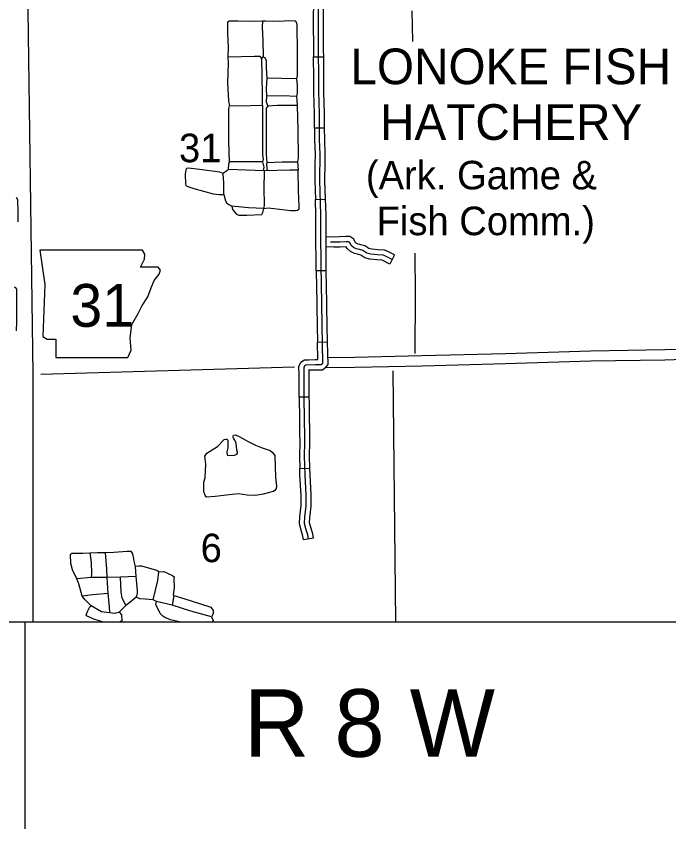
# Model space of a CAD drawing. Extents: x 1127717 to 1741049, y 2026793 to 2244711.
# Drawn here: x 1338119 to 1347778, y 2063612 to 2075639 of the extents above; entities that cross this region are included whole.
import ezdxf

# ---------------------------------------------------------------- set-up
doc = ezdxf.new("R2010")
doc.units = 0
for name, color, linetype in [('1', 7, 'Continuous'), ('10', 7, 'Continuous'), ('21', 7, 'Continuous'), ('31', 7, 'Continuous'), ('35', 7, 'Continuous'), ('37', 7, 'Continuous'), ('4', 7, 'Continuous'), ('45', 7, 'Continuous'), ('46', 7, 'Continuous'), ('5', 7, 'Continuous'), ('7', 7, 'Continuous'), ('R_Draft', 7, 'Continuous')]:
    doc.layers.add(name, color=color, linetype=linetype)

msp = doc.modelspace()

# ---------------------------------------------------------------- linework, layer by layer
at = {"layer": '1'}
msp.add_line((1338244, 2066677), (1338244, 2063612), dxfattribs=at)
msp.add_lwpolyline([(1349634, 2111942), (1278363, 2111942), (1278363, 2066677), (1349634, 2066677)], close=True, dxfattribs=at)
at = {"layer": '10'}
for points in [[(1338278, 2076445), (1338363, 2070341)], [(1338363, 2070339), (1338362, 2066677)]]:
    msp.add_lwpolyline(points, dxfattribs=at)
at = {"layer": '21'}
msp.add_lwpolyline([(1338468, 2072178), (1338544, 2071670), (1338510, 2070900), (1338578, 2070858), (1338705, 2070858), (1338705, 2070587), (1339771, 2070587), (1339821, 2070697), (1339804, 2070875), (1339830, 2071078), (1339923, 2071239), (1339982, 2071357), (1340067, 2071484), (1340117, 2071619), (1340160, 2071729), (1340236, 2071822), (1340253, 2071882), (1340219, 2071924), (1339957, 2071924), (1340016, 2072042), (1340024, 2072118), (1339989, 2072177)], close=True, dxfattribs=at)
at = {"layer": '31'}
for p, q in [((1342520, 2075038), (1342670, 2075039)), ((1342684, 2073983), (1342534, 2073982)), ((1342548, 2072924), (1342697, 2072929)), ((1342709, 2071872), (1342559, 2071869)), ((1342709, 2071872), (1342709, 2071872)), ((1342577, 2070813), (1342727, 2070817)), ((1342457, 2070002), (1342307, 2070002)), ((1342316, 2068944), (1342466, 2068948)), ((1342518, 2067911), (1342369, 2067888))]:
    msp.add_line(p, q, dxfattribs=at)
for points in [[(1342515, 2076093), (1342516, 2075947), (1342519, 2075852), (1342516, 2075591), (1342516, 2075566)], [(1342666, 2075567), (1342666, 2075590), (1342669, 2075854), (1342666, 2075950), (1342665, 2076095)], [(1342444, 2067900), (1342434, 2067961), (1342412, 2068034), (1342386, 2068131), (1342390, 2068222), (1342400, 2068306), (1342411, 2068391), (1342411, 2068551), (1342394, 2068853), (1342386, 2069125), (1342390, 2069333), (1342386, 2069748), (1342383, 2069921), (1342381, 2070338), (1342379, 2070441), (1342390, 2070468), (1342406, 2070477), (1342544, 2070482), (1342628, 2070482), (1342650, 2070497), (1342659, 2070510), (1342646, 2071056), (1342642, 2071395), (1342633, 2071945), (1342630, 2072444), (1342630, 2072697), (1342614, 2073211), (1342617, 2073595), (1342610, 2073813), (1342607, 2074196), (1342598, 2074529), (1342598, 2074724), (1342594, 2075137), (1342591, 2075591), (1342594, 2075853)], [(1342516, 2075566), (1342519, 2075136), (1342520, 2075038)], [(1342670, 2075039), (1342669, 2075137), (1342666, 2075567)], [(1342523, 2074508), (1342523, 2074528), (1342523, 2074724), (1342520, 2075038)], [(1342673, 2074512), (1342673, 2074530), (1342673, 2074724), (1342670, 2075039)], [(1342534, 2073982), (1342532, 2074195), (1342523, 2074508)], [(1342684, 2073983), (1342682, 2074198), (1342673, 2074512)], [(1342534, 2073982), (1342535, 2073811), (1342542, 2073594), (1342541, 2073455)], [(1342691, 2073454), (1342692, 2073596), (1342685, 2073814), (1342684, 2073983)], [(1342541, 2073455), (1342539, 2073211), (1342548, 2072924)], [(1342697, 2072929), (1342689, 2073212), (1342691, 2073454)], [(1342555, 2072398), (1342555, 2072444), (1342555, 2072695), (1342548, 2072924)], [(1342705, 2072399), (1342705, 2072444), (1342705, 2072698), (1342697, 2072929)], [(1342559, 2071869), (1342558, 2071944), (1342555, 2072398)], [(1342709, 2071872), (1342708, 2071946), (1342705, 2072399)], [(1342559, 2071869), (1342567, 2071394), (1342568, 2071342)], [(1342718, 2071344), (1342717, 2071396), (1342709, 2071872)], [(1342568, 2071342), (1342571, 2071055), (1342577, 2070813)], [(1342727, 2070817), (1342721, 2071057), (1342718, 2071344)], [(1342445, 2070553), (1342542, 2070557), (1342583, 2070557), (1342577, 2070813)], [(1342451, 2070403), (1342545, 2070407), (1342652, 2070407), (1342703, 2070443), (1342735, 2070486), (1342727, 2070817)], [(1342307, 2070002), (1342306, 2070337), (1342304, 2070455), (1342331, 2070519), (1342384, 2070551), (1342445, 2070553)], [(1342457, 2070002), (1342456, 2070338), (1342455, 2070404), (1342451, 2070403)], [(1342307, 2070002), (1342308, 2069921), (1342311, 2069747), (1342314, 2069473)], [(1342464, 2069475), (1342461, 2069749), (1342458, 2069922), (1342457, 2070002)], [(1342314, 2069473), (1342315, 2069333), (1342311, 2069125), (1342316, 2068944)], [(1342466, 2068948), (1342461, 2069125), (1342465, 2069333), (1342464, 2069475)], [(1342336, 2068419), (1342336, 2068548), (1342319, 2068849), (1342316, 2068944)], [(1342486, 2068419), (1342486, 2068553), (1342469, 2068856), (1342466, 2068948)], [(1342369, 2067888), (1342361, 2067944), (1342340, 2068014), (1342310, 2068123), (1342316, 2068228), (1342325, 2068315), (1342336, 2068396), (1342336, 2068419)], [(1342518, 2067911), (1342508, 2067977), (1342484, 2068055), (1342461, 2068139), (1342465, 2068216), (1342474, 2068297), (1342486, 2068386), (1342486, 2068419)]]:
    msp.add_lwpolyline(points, dxfattribs=at)
at = {"layer": '35'}
for points in [[(1341764, 2075564), (1341632, 2075562), (1341397, 2075564), (1341304, 2075568), (1341270, 2075568), (1341256, 2075560), (1341248, 2075547), (1341248, 2075394), (1341254, 2075173), (1341252, 2075035), (1341254, 2074944), (1341248, 2074655), (1341260, 2074380), (1341274, 2074314)], [(1342284, 2074320), (1342276, 2074390), (1342274, 2074453), (1342284, 2074501), (1342284, 2074617), (1342272, 2074712), (1342280, 2074764), (1342282, 2075092), (1342278, 2075515), (1342264, 2075555), (1342248, 2075568), (1342156, 2075570), (1342017, 2075560), (1341810, 2075568), (1341764, 2075564), (1341760, 2075481), (1341768, 2075278), (1341774, 2075037)], [(1341754, 2075013), (1341729, 2075041), (1341646, 2075043), (1341252, 2075035)], [(1341762, 2074320), (1341762, 2074483), (1341754, 2075013), (1341774, 2075037), (1341798, 2075029), (1341818, 2074983), (1341820, 2074876), (1341827, 2074724), (1341818, 2074576), (1341825, 2074455), (1341816, 2074372), (1341843, 2074309)], [(1342272, 2074712), (1342043, 2074718), (1341827, 2074724)], [(1342274, 2074453), (1342059, 2074463), (1341825, 2074455)], [(1341262, 2073372), (1341264, 2073454), (1341274, 2073486), (1341266, 2073789), (1341268, 2074273), (1341274, 2074314), (1341588, 2074320), (1341727, 2074324), (1341762, 2074320), (1341766, 2073990), (1341766, 2073581), (1341772, 2073528), (1341764, 2073486), (1341786, 2073407), (1341776, 2073353)], [(1342296, 2073360), (1342288, 2073484), (1342298, 2073543), (1342290, 2073953), (1342284, 2074320), (1341988, 2074316), (1341843, 2074309), (1341816, 2074277), (1341818, 2074168), (1341820, 2073593), (1341827, 2073476), (1341823, 2073447), (1341829, 2073389), (1341831, 2073353)], [(1341764, 2073486), (1341434, 2073484), (1341274, 2073486)], [(1341827, 2073476), (1342053, 2073482), (1342288, 2073484)], [(1342296, 2073360), (1342171, 2073358), (1341790, 2073352), (1341521, 2073358), (1341262, 2073372), (1341235, 2073352), (1341183, 2073313), (1341130, 2073333), (1340831, 2073370), (1340671, 2073392), (1340640, 2073386), (1340628, 2073366), (1340620, 2073299), (1340622, 2073153), (1340630, 2073131), (1340657, 2073121), (1340746, 2073089), (1341033, 2073010), (1341124, 2072998), (1341155, 2073002), (1341191, 2073002), (1341217, 2072904), (1341235, 2072870), (1341266, 2072852), (1341308, 2072828), (1341320, 2072777), (1341373, 2072712), (1341408, 2072692), (1341531, 2072692), (1341756, 2072702), (1341770, 2072732), (1341784, 2072791), (1341849, 2072803), (1342185, 2072761), (1342254, 2072761), (1342280, 2072767), (1342306, 2072789), (1342306, 2072823), (1342296, 2073060), (1342294, 2073356)], [(1341790, 2073352), (1341786, 2073080), (1341788, 2072860), (1341784, 2072791)], [(1341191, 2073002), (1341191, 2073168), (1341183, 2073313)], [(1338146, 2072594), (1338146, 2072746), (1338141, 2072920), (1338120, 2072957)], [(1341784, 2072791), (1341555, 2072805), (1341308, 2072828)], [(1338123, 2070982), (1338128, 2071114), (1338126, 2071283), (1338128, 2071528), (1338128, 2071601), (1338113, 2071621), (1338095, 2071627)], [(1341946, 2069136), (1341956, 2068817), (1341971, 2068684), (1341968, 2068648), (1341946, 2068619), (1341920, 2068605), (1341772, 2068564), (1341659, 2068546), (1341538, 2068552), (1341411, 2068568), (1341316, 2068558), (1341065, 2068530), (1340939, 2068522), (1340930, 2068527), (1340918, 2068539), (1340896, 2068597), (1340896, 2068740), (1340915, 2068807), (1340925, 2069007), (1340911, 2069128), (1340942, 2069171), (1341099, 2069268), (1341198, 2069374), (1341222, 2069379), (1341236, 2069379), (1341249, 2069362), (1341249, 2069334), (1341249, 2069251), (1341237, 2069193), (1341237, 2069174), (1341241, 2069153), (1341244, 2069143), (1341266, 2069138), (1341352, 2069140), (1341386, 2069155), (1341393, 2069169), (1341393, 2069186), (1341384, 2069217), (1341376, 2069317), (1341353, 2069363), (1341333, 2069392), (1341328, 2069401), (1341328, 2069430), (1341336, 2069437), (1341364, 2069444), (1341418, 2069420), (1341553, 2069343), (1341662, 2069290)], [(1341662, 2069290), (1341761, 2069249), (1341879, 2069211), (1341906, 2069188), (1341946, 2069136)], [(1339880, 2067495), (1339888, 2067348), (1339911, 2067139), (1339911, 2067084), (1339898, 2067062), (1339894, 2067041), (1339800, 2066959), (1339743, 2066914), (1339643, 2066816), (1339576, 2066800), (1339500, 2066806), (1339380, 2066823), (1339229, 2066912), (1339141, 2066998), (1339096, 2067057), (1339047, 2067239), (1339018, 2067311), (1338953, 2067444), (1338926, 2067538), (1338924, 2067670), (1338943, 2067691), (1338982, 2067693), (1339106, 2067689), (1339206, 2067695), (1339321, 2067703), (1339437, 2067703), (1339564, 2067707), (1339762, 2067723), (1339813, 2067719), (1339837, 2067693), (1339845, 2067662), (1339860, 2067572), (1339880, 2067495)], [(1339206, 2067695), (1339227, 2067554), (1339231, 2067388), (1339229, 2067329)], [(1339437, 2067703), (1339453, 2067456), (1339461, 2067331), (1339476, 2067092), (1339494, 2066904), (1339500, 2066806)], [(1340231, 2067415), (1340199, 2067433), (1339980, 2067501), (1339935, 2067501), (1339880, 2067495)], [(1339888, 2067348), (1339664, 2067335), (1339461, 2067331), (1339229, 2067329), (1339018, 2067311)], [(1339743, 2066914), (1339686, 2067031), (1339674, 2067115), (1339664, 2067335)], [(1340146, 2067000), (1340213, 2067286), (1340231, 2067415)], [(1340231, 2067415), (1340301, 2067419), (1340433, 2067360), (1340454, 2067341), (1340452, 2067315), (1340458, 2067178), (1340442, 2067076), (1340452, 2067064), (1340613, 2067017), (1340971, 2066904), (1340997, 2066890), (1341034, 2066841), (1341036, 2066800), (1341030, 2066784), (1341009, 2066751)], [(1339476, 2067092), (1339251, 2067076), (1339096, 2067057)], [(1341009, 2066751), (1340705, 2066833), (1340427, 2066919), (1340197, 2066976), (1340146, 2067000), (1340025, 2067010), (1339949, 2067017), (1339894, 2067041)], [(1340537, 2066677), (1340401, 2066706), (1340319, 2066737), (1340291, 2066757), (1340248, 2066800), (1340184, 2066929), (1340197, 2066976)], [(1340452, 2067064), (1340427, 2066919)], [(1339396, 2066677), (1339265, 2066716), (1339159, 2066761), (1339155, 2066776), (1339176, 2066837), (1339202, 2066886), (1339229, 2066912)], [(1339643, 2066816), (1339676, 2066778), (1339680, 2066688), (1339657, 2066677)], [(1341009, 2066751), (1341036, 2066694), (1341021, 2066677)]]:
    msp.add_lwpolyline(points, dxfattribs=at)
at = {"layer": '37'}
msp.add_lwpolyline([(1338468, 2066677), (1338468, 2066677)], dxfattribs=at)
at = {"layer": '4'}
msp.add_lwpolyline([(1338482, 2070340), (1342237, 2070450)], dxfattribs=at)
at = {"layer": '45'}
msp.add_line((1343717, 2072105), (1343650, 2071971), dxfattribs=at)
for points in [[(1343205, 2072261), (1343178, 2072267), (1343152, 2072281), (1343137, 2072293), (1343114, 2072339), (1343058, 2072377), (1343003, 2072377), (1342906, 2072372), (1342821, 2072370), (1342705, 2072375)], [(1343684, 2072038), (1343577, 2072092), (1343551, 2072103), (1343464, 2072106), (1343369, 2072117), (1343308, 2072134), (1343250, 2072169), (1343198, 2072185), (1343152, 2072197), (1343110, 2072218), (1343077, 2072246), (1343056, 2072288), (1343035, 2072302), (1343005, 2072302), (1342909, 2072297), (1342820, 2072295), (1342772, 2072297)], [(1343717, 2072105), (1343609, 2072159), (1343568, 2072178), (1343470, 2072181), (1343383, 2072191), (1343338, 2072203), (1343281, 2072238), (1343219, 2072257), (1343205, 2072261)], [(1343168, 2072115), (1343126, 2072126), (1343068, 2072155), (1343017, 2072199), (1343003, 2072227), (1342912, 2072222), (1342820, 2072220), (1342706, 2072225)], [(1343650, 2071971), (1343544, 2072024), (1343534, 2072029), (1343459, 2072031), (1343354, 2072044), (1343279, 2072064), (1343219, 2072100), (1343178, 2072113), (1343168, 2072115)]]:
    msp.add_lwpolyline(points, dxfattribs=at)
at = {"layer": '46'}
for points in [[(1349054, 2070738), (1347718, 2070700), (1346623, 2070682), (1345359, 2070643), (1344124, 2070611), (1343130, 2070588), (1342733, 2070582)], [(1348942, 2070592), (1347722, 2070550), (1346626, 2070533), (1345363, 2070493), (1344128, 2070461), (1343132, 2070438), (1342687, 2070432)]]:
    msp.add_lwpolyline(points, dxfattribs=at)
at = {"layer": '5'}
for points in [[(1343973, 2075717), (1343985, 2075266)], [(1344019, 2072132), (1344026, 2071529), (1344021, 2070646)], [(1343694, 2070391), (1343732, 2066677)]]:
    msp.add_lwpolyline(points, dxfattribs=at)

# ---------------------------------------------------------------- texts
at = {"layer": '21'}
msp.add_text('31', height=633.6, dxfattribs=at).set_placement((1338920, 2071042))
at = {"layer": '5'}
for s, height, p in [('31', 422.4, (1340528, 2073478)), ('6', 422, (1340848, 2067558))]:
    msp.add_text(s, height=height, dxfattribs=at).set_placement(p)
at = {"layer": '7'}
for s, height, p in [('LONOKE FISH', 528, (1343065, 2074633)), ('HATCHERY', 528, (1343503, 2073809)), ('(Ark. Game &', 422.4, (1343295, 2073076)), ('Fish Comm.)', 422.4, (1343453, 2072398))]:
    msp.add_text(s, height=height, dxfattribs=at).set_placement(p)
at = {"layer": 'R_Draft'}
msp.add_text('R 8 W', height=1000, dxfattribs=at).set_placement((1341491, 2064677))

doc.saveas('drawing.dxf')
